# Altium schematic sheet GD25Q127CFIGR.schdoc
size 127 x 101 mm
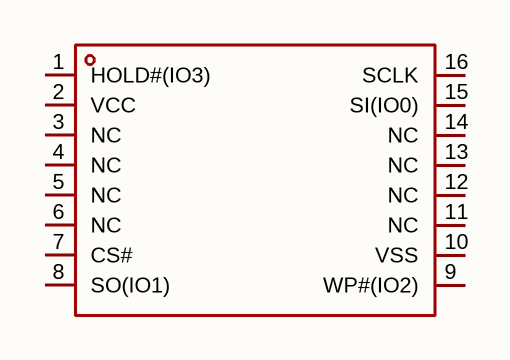
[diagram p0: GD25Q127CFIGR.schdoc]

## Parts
U?  gd25q127cfigr  [SOIC-16_L10.3-W7.5-P1.27-LS10.3-BL]  (value not drawn)

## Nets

Not connected (* = marked no-connect by the designer): U? 1(HOLD#(IO3)) 2(VCC) 3(NC) 4(NC) 5(NC) 6(NC) 7(CS#) 8(SO(IO1)) 9(WP#(IO2)) 10(VSS) 11(NC) 12(NC) 13(NC) 14(NC) 15(SI(IO0)) 16(SCLK)

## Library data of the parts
U? = gd25q127cfigr: 接口类型:SPI;存储容量:128Mbit;时钟频率(fc):104MHz;; Manufacturer: GigaDevice(兆易创新); AddInBom: yes; ModelId: 2da8125c657e49328ba6fa7b098653dd; ModelName: SOIC-16_L10.3-W7.5-H2.7-LS10.3-P1.27; ModelTransform: 405.511,409.68154,0,0,0,0,-0.0005,0,0; Interface: SPI; Clock Frequency: 104MHz; Voltage - Supply: 2.7V~3.6V; Standby Supply Current: 20uA; Program / Erase Cycles: 100000次; Page Programming Time (Tpp): 500us; Block Erase Time(tBE): 300ms@(64KB); Data Retention - TDR (Year): 20年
